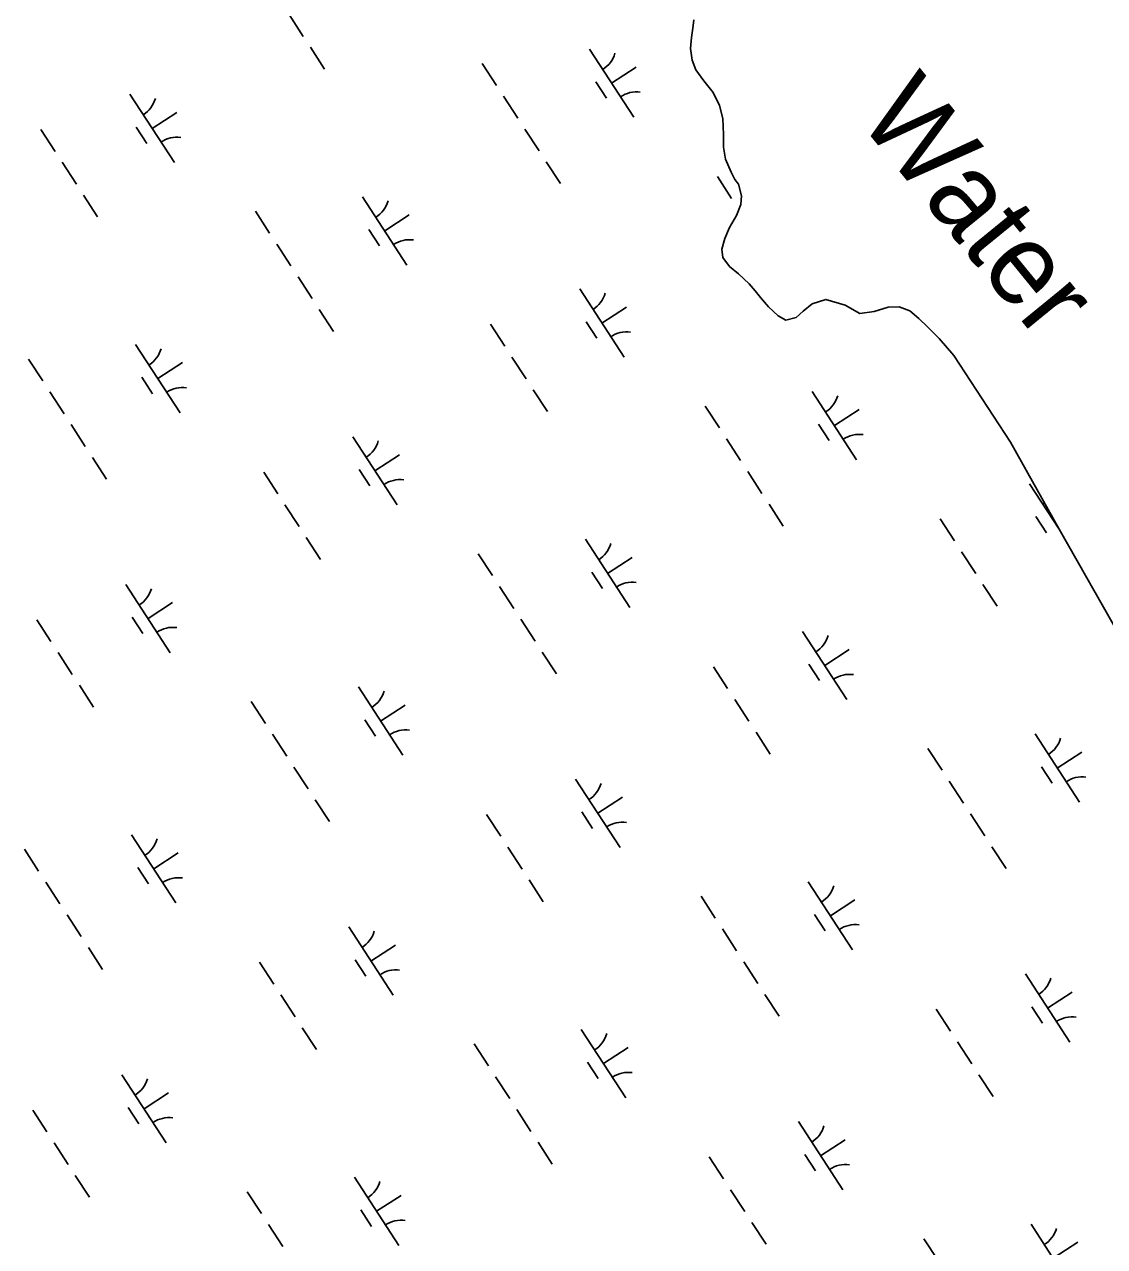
# Model space of a CAD drawing. Extents: x 3953924 to 3974542, y 193747 to 216192.
# Drawn here: x 3966671 to 3967335, y 205029 to 205780 of the extents above; entities that cross this region are included whole.
import ezdxf

# ---------------------------------------------------------------- set-up
doc = ezdxf.new("R2010")
doc.units = 0
for name, color, linetype in [('V-RIVR-IDEN', 7, 'Continuous'), ('V-TOPO-SHOR', 7, 'Continuous'), ('V-WETL-SWMP', 7, 'Continuous')]:
    doc.layers.add(name, color=color, linetype=linetype)

msp = doc.modelspace()

# ---------------------------------------------------------------- linework, layer by layer
at = {"layer": 'V-TOPO-SHOR'}
msp.add_lwpolyline([(3967082.61, 205782.77), (3967081.95, 205777.58), (3967081.04, 205771.89), (3967080.62, 205765.17), (3967081.47, 205757.95), (3967083.85, 205751.99), (3967088.63, 205745.25), (3967094.42, 205738), (3967098.43, 205730.12), (3967100.42, 205722.14), (3967100.87, 205712.25), (3967100.71, 205704.4), (3967102.06, 205697.05), (3967105.57, 205689.18), (3967107.83, 205684.61), (3967109.96, 205681.68), (3967111.83, 205674.58), (3967111.55, 205669.26), (3967108.73, 205662.44), (3967104.51, 205655.24), (3967101.56, 205648.41), (3967099.76, 205641.83), (3967100.49, 205636.76), (3967104.52, 205631.17), (3967109.94, 205626.71), (3967116.62, 205620.6), (3967120.27, 205616.27), (3967123.55, 205612.08), (3967128.46, 205606.35), (3967134.38, 205600.88), (3967139.06, 205598.19), (3967145.52, 205599.93), (3967149.72, 205603.84), (3967155.19, 205608.37), (3967163.69, 205610.99), (3967175.58, 205607.38), (3967184.55, 205602.27), (3967193.42, 205603.49), (3967201.92, 205606.24), (3967208.63, 205606.45), (3967215.21, 205604.01), (3967220.88, 205599.17), (3967226.18, 205594.21), (3967233.23, 205587.08), (3967242.3, 205576.64), (3967277.12, 205523.27), (3967306.99, 205469.8), (3967345.41, 205402.6)], dxfattribs=at)
at = {"layer": 'V-WETL-SWMP'}
for p, q in [((3966833.87, 205785.93), (3966842.6, 205772.52)), ((3967081.95, 205777.58), (3967082.61, 205782.77)), ((3967081.04, 205771.89), (3967081.95, 205777.58)), ((3966846.96, 205765.82), (3966855.69, 205752.41)), ((3967018.42, 205764.77), (3967045.7, 205722.86)), ((3967080.62, 205765.17), (3967081.04, 205771.89)), ((3967081.47, 205757.95), (3967080.62, 205765.17)), ((3967083.85, 205751.99), (3967081.47, 205757.95)), ((3966952.6, 205755.83), (3966961.33, 205742.43)), ((3967032.06, 205743.81), (3967047.14, 205753.63)), ((3967088.63, 205745.25), (3967083.85, 205751.99)), ((3967022.32, 205744.63), (3967028.87, 205734.58)), ((3967094.42, 205738), (3967088.63, 205745.25)), ((3966736.13, 205736.98), (3966763.4, 205695.08)), ((3966965.69, 205735.72), (3966974.42, 205722.31)), ((3967098.43, 205730.12), (3967094.42, 205738)), ((3967100.42, 205722.14), (3967098.43, 205730.12)), ((3966749.76, 205716.03), (3966764.85, 205725.85)), ((3967100.87, 205712.25), (3967100.42, 205722.14)), ((3966681.37, 205715.3), (3966690.1, 205701.89)), ((3966740.02, 205716.85), (3966746.57, 205706.79)), ((3966978.79, 205715.61), (3966987.52, 205702.2)), ((3967100.71, 205704.4), (3967100.87, 205712.25)), ((3967102.06, 205697.05), (3967100.71, 205704.4)), ((3967105.57, 205689.18), (3967102.06, 205697.05)), ((3966694.46, 205695.19), (3966703.19, 205681.78)), ((3966991.88, 205695.49), (3967000.61, 205682.08)), ((3967097.09, 205686.47), (3967105.81, 205673.06)), ((3967107.83, 205684.61), (3967105.57, 205689.18)), ((3967109.96, 205681.68), (3967107.83, 205684.61)), ((3966707.56, 205675.08), (3966716.28, 205661.67)), ((3967111.83, 205674.58), (3967109.96, 205681.68)), ((3967111.55, 205669.26), (3967111.83, 205674.58)), ((3966879.02, 205674.02), (3966906.29, 205632.12)), ((3967108.73, 205662.44), (3967111.55, 205669.26)), ((3966813.2, 205665.09), (3966821.92, 205651.68)), ((3966892.65, 205653.07), (3966907.74, 205662.89)), ((3967104.51, 205655.24), (3967108.73, 205662.44)), ((3967110.18, 205666.36), (3967110.28, 205666.2)), ((3966882.92, 205653.89), (3966889.46, 205643.83)), ((3967101.56, 205648.41), (3967104.51, 205655.24)), ((3966826.29, 205644.98), (3966835.02, 205631.57)), ((3967099.76, 205641.84), (3967101.56, 205648.41)), ((3967100.49, 205636.77), (3967099.76, 205641.84)), ((3967104.52, 205631.17), (3967100.49, 205636.77)), ((3967109.94, 205626.71), (3967104.52, 205631.17)), ((3966839.38, 205624.86), (3966848.11, 205611.45)), ((3967116.62, 205620.6), (3967109.94, 205626.71)), ((3967012.44, 205617.41), (3967039.71, 205575.5)), ((3967120.27, 205616.27), (3967116.62, 205620.6)), ((3967123.55, 205612.08), (3967120.27, 205616.27)), ((3967128.46, 205606.35), (3967123.55, 205612.08)), ((3967155.19, 205608.37), (3967149.72, 205603.84)), ((3967163.69, 205610.99), (3967155.19, 205608.37)), ((3967175.58, 205607.38), (3967163.69, 205610.99)), ((3967184.55, 205602.27), (3967175.58, 205607.38)), ((3966852.48, 205604.75), (3966861.2, 205591.34)), ((3967026.08, 205596.45), (3967041.16, 205606.27)), ((3967134.38, 205600.88), (3967128.46, 205606.35)), ((3967139.06, 205598.19), (3967134.38, 205600.88)), ((3967145.52, 205599.93), (3967139.06, 205598.19)), ((3967149.72, 205603.84), (3967145.52, 205599.93)), ((3967193.42, 205603.49), (3967184.55, 205602.27)), ((3967201.92, 205606.23), (3967193.42, 205603.49)), ((3967208.63, 205606.45), (3967201.92, 205606.23)), ((3967215.21, 205604.01), (3967208.63, 205606.45)), ((3967220.88, 205599.17), (3967215.21, 205604.01)), ((3966957.68, 205595.73), (3966966.41, 205582.32)), ((3967016.34, 205597.27), (3967022.88, 205587.22)), ((3967226.18, 205594.21), (3967220.88, 205599.17)), ((3967233.23, 205587.08), (3967226.18, 205594.21)), ((3967242.3, 205576.64), (3967233.23, 205587.08)), ((3966739.61, 205583.28), (3966766.89, 205541.37)), ((3966673.79, 205574.35), (3966682.52, 205560.94)), ((3966753.25, 205562.33), (3966768.34, 205572.15)), ((3966970.77, 205575.61), (3966979.5, 205562.2)), ((3967277.12, 205523.27), (3967242.3, 205576.64)), ((3966743.51, 205563.14), (3966750.06, 205553.09)), ((3966983.87, 205555.5), (3966992.6, 205542.09)), ((3967155.33, 205554.45), (3967182.6, 205512.54)), ((3966686.88, 205554.23), (3966695.61, 205540.82)), ((3967089.51, 205545.51), (3967098.24, 205532.11)), ((3967168.97, 205533.49), (3967184.05, 205543.31)), ((3966699.98, 205534.12), (3966708.71, 205520.71)), ((3967159.23, 205534.31), (3967165.77, 205524.26)), ((3966873.03, 205526.66), (3966900.31, 205484.76)), ((3967102.6, 205525.4), (3967111.33, 205511.99)), ((3967306.99, 205469.79), (3967277.12, 205523.27)), ((3966713.07, 205514), (3966721.8, 205500.59)), ((3966886.67, 205505.71), (3966901.76, 205515.53)), ((3966818.28, 205504.98), (3966827.01, 205491.57)), ((3966876.93, 205506.53), (3966883.48, 205496.47)), ((3967115.69, 205505.29), (3967124.42, 205491.88)), ((3967288.75, 205497.83), (3967306.95, 205469.87)), ((3966831.37, 205484.87), (3966840.1, 205471.46)), ((3967128.79, 205485.17), (3967137.51, 205471.76)), ((3967233.99, 205476.15), (3967242.72, 205462.74)), ((3967292.65, 205477.7), (3967299.19, 205467.64)), ((3967302.39, 205476.88), (3967302.86, 205477.19)), ((3966844.46, 205464.76), (3966853.19, 205451.35)), ((3967345.41, 205402.6), (3967306.99, 205469.79)), ((3967015.92, 205463.7), (3967043.2, 205421.8)), ((3966950.1, 205454.77), (3966958.83, 205441.36)), ((3967029.56, 205442.75), (3967044.65, 205452.57)), ((3967247.09, 205456.04), (3967255.81, 205442.63)), ((3967019.82, 205443.57), (3967026.37, 205433.51)), ((3966733.63, 205435.92), (3966760.91, 205394.01)), ((3966963.2, 205434.66), (3966971.92, 205421.25)), ((3967260.18, 205435.93), (3967268.91, 205422.52)), ((3966747.27, 205414.96), (3966762.35, 205424.78)), ((3966678.87, 205414.24), (3966687.6, 205400.83)), ((3966737.53, 205415.78), (3966744.07, 205405.73)), ((3966976.29, 205414.54), (3966985.02, 205401.13)), ((3967149.34, 205407.09), (3967176.62, 205365.18)), ((3966691.97, 205394.13), (3966700.69, 205380.72)), ((3966989.38, 205394.43), (3966998.11, 205381.02)), ((3967162.98, 205386.13), (3967178.07, 205395.95)), ((3967094.59, 205385.41), (3967103.32, 205372)), ((3967153.24, 205386.95), (3967159.79, 205376.9)), ((3966705.06, 205374.01), (3966713.79, 205360.6)), ((3966876.52, 205372.96), (3966903.8, 205331.05)), ((3966810.7, 205364.03), (3966819.43, 205350.62)), ((3966890.16, 205352.01), (3966905.24, 205361.83)), ((3967107.68, 205365.29), (3967116.41, 205351.89)), ((3966880.42, 205352.82), (3966886.96, 205342.77)), ((3967120.77, 205345.18), (3967129.5, 205331.77)), ((3966823.79, 205343.91), (3966832.52, 205330.5)), ((3967292.23, 205344.13), (3967319.51, 205302.22)), ((3967226.41, 205335.19), (3967235.14, 205321.79)), ((3967305.87, 205323.17), (3967320.96, 205332.99)), ((3966836.88, 205323.8), (3966845.61, 205310.39)), ((3967296.13, 205323.99), (3967302.68, 205313.94)), ((3967009.94, 205316.34), (3967037.22, 205274.44)), ((3967239.51, 205315.08), (3967248.24, 205301.67)), ((3966849.98, 205303.68), (3966858.71, 205290.27)), ((3967023.58, 205295.39), (3967038.66, 205305.21)), ((3966955.18, 205294.66), (3966963.91, 205281.25)), ((3967013.84, 205296.21), (3967020.38, 205286.15)), ((3967252.6, 205294.97), (3967261.33, 205281.56)), ((3966737.11, 205282.21), (3966764.39, 205240.31)), ((3966671.29, 205273.28), (3966680.02, 205259.87)), ((3966750.75, 205261.26), (3966765.84, 205271.08)), ((3966968.28, 205274.55), (3966977.01, 205261.14)), ((3967265.69, 205274.85), (3967274.42, 205261.44)), ((3966741.01, 205262.08), (3966747.56, 205252.02)), ((3966981.37, 205254.44), (3966990.1, 205241.03)), ((3966684.39, 205253.17), (3966693.12, 205239.76)), ((3967152.83, 205253.38), (3967180.11, 205211.48)), ((3967087.01, 205244.45), (3967095.74, 205231.04)), ((3967166.47, 205232.43), (3967181.55, 205242.25)), ((3966697.48, 205233.05), (3966706.21, 205219.64)), ((3967156.73, 205233.25), (3967163.28, 205223.19)), ((3966870.53, 205225.6), (3966897.81, 205183.69)), ((3967100.1, 205224.34), (3967108.83, 205210.93)), ((3966710.57, 205212.94), (3966719.3, 205199.53)), ((3966884.17, 205204.64), (3966899.26, 205214.46)), ((3966815.78, 205203.92), (3966824.51, 205190.51)), ((3966874.43, 205205.46), (3966880.98, 205195.41)), ((3967113.2, 205204.22), (3967121.92, 205190.81)), ((3967286.25, 205196.77), (3967313.53, 205154.86)), ((3966828.87, 205183.81), (3966837.6, 205170.4)), ((3967126.29, 205184.11), (3967135.02, 205170.7)), ((3967299.89, 205175.81), (3967314.97, 205185.63)), ((3967231.49, 205175.09), (3967240.22, 205161.68)), ((3967290.15, 205176.63), (3967296.7, 205166.58)), ((3966841.97, 205163.69), (3966850.69, 205150.28)), ((3967013.42, 205162.64), (3967040.7, 205120.73)), ((3966947.6, 205153.71), (3966956.33, 205140.3)), ((3967027.06, 205141.69), (3967042.15, 205151.51)), ((3967244.59, 205154.97), (3967253.32, 205141.57)), ((3967017.32, 205142.5), (3967023.87, 205132.45)), ((3966731.13, 205134.85), (3966758.41, 205092.95)), ((3967257.68, 205134.86), (3967266.41, 205121.45)), ((3966960.7, 205133.59), (3966969.43, 205120.18)), ((3966744.77, 205113.9), (3966759.85, 205123.72)), ((3966676.37, 205113.17), (3966685.1, 205099.77)), ((3966735.03, 205114.72), (3966741.58, 205104.66)), ((3966973.79, 205113.48), (3966982.52, 205100.07)), ((3967146.85, 205106.02), (3967174.12, 205064.12)), ((3966689.47, 205093.06), (3966698.2, 205079.65)), ((3966986.88, 205093.36), (3966995.61, 205079.95)), ((3967160.48, 205085.07), (3967175.57, 205094.89)), ((3967092.09, 205084.34), (3967100.82, 205070.93)), ((3967150.75, 205085.89), (3967157.29, 205075.83)), ((3966702.56, 205072.95), (3966711.29, 205059.54)), ((3966874.02, 205071.89), (3966901.3, 205029.99)), ((3966808.2, 205062.96), (3966816.93, 205049.55)), ((3966887.66, 205050.94), (3966902.74, 205060.76)), ((3967105.18, 205064.23), (3967113.91, 205050.82)), ((3966877.92, 205051.76), (3966884.47, 205041.7)), ((3967118.28, 205044.12), (3967127, 205030.71)), ((3966821.29, 205042.85), (3966830.02, 205029.44)), ((3967289.74, 205043.06), (3967317.01, 205001.16)), ((3967223.92, 205034.13), (3967232.64, 205020.72)), ((3967303.37, 205022.11), (3967318.46, 205031.93))]:
    msp.add_line(p, q, dxfattribs=at)
for centre, start, end in [((3967017.19, 205767.09), 302.29009, 343.83375), ((3967047.33, 205720.8), 82.29009, 123.83375), ((3966734.89, 205739.31), 302.29009, 343.83375), ((3966765.03, 205693.01), 82.29009, 123.83375), ((3966877.78, 205676.35), 302.29009, 343.83375), ((3966907.92, 205630.05), 82.29009, 123.83375), ((3967011.21, 205619.73), 302.29009, 343.83375), ((3967041.34, 205573.43), 82.29009, 123.83375), ((3966738.38, 205585.6), 302.29009, 343.83375), ((3966768.52, 205539.31), 82.29009, 123.83375), ((3967154.1, 205556.77), 302.29009, 343.83375), ((3967184.23, 205510.48), 82.29009, 123.83375), ((3966871.8, 205528.99), 302.29009, 343.83375), ((3966901.94, 205482.69), 82.29009, 123.83375), ((3967287.52, 205500.16), 302.29009, 306.33799), ((3967014.69, 205466.03), 302.29009, 343.83375), ((3967044.83, 205419.73), 82.29009, 123.83375), ((3966732.4, 205438.24), 302.29009, 343.83375), ((3966762.53, 205391.95), 82.29009, 123.83375), ((3967148.11, 205409.41), 302.29009, 343.83375), ((3967178.25, 205363.11), 82.29009, 123.83375), ((3966875.29, 205375.28), 302.29009, 343.83375), ((3966905.42, 205328.99), 82.29009, 123.83375), ((3967291, 205346.45), 302.29009, 343.83375), ((3967321.14, 205300.16), 82.29009, 123.83375), ((3967008.71, 205318.67), 302.29009, 343.83375), ((3967038.85, 205272.37), 82.29009, 123.83375), ((3966735.88, 205284.54), 302.29009, 343.83375), ((3966766.02, 205238.24), 82.29009, 123.83375), ((3967151.6, 205255.71), 302.29009, 343.83375), ((3967181.74, 205209.41), 82.29009, 123.83375), ((3966869.3, 205227.92), 302.29009, 343.83375), ((3966899.44, 205181.63), 82.29009, 123.83375), ((3967285.02, 205199.09), 302.29009, 343.83375), ((3967315.16, 205152.79), 82.29009, 123.83375), ((3967012.19, 205164.96), 302.29009, 343.83375), ((3967042.33, 205118.67), 82.29009, 123.83375), ((3966729.9, 205137.18), 302.29009, 343.83375), ((3966760.04, 205090.88), 82.29009, 123.83375), ((3967145.61, 205108.35), 302.29009, 343.83375), ((3967175.75, 205062.05), 82.29009, 123.83375), ((3966872.79, 205074.22), 302.29009, 343.83375), ((3966902.93, 205027.92), 82.29009, 123.83375), ((3967288.5, 205045.39), 302.29009, 343.83375)]:
    msp.add_arc(centre, 17.62, start, end, dxfattribs=at)

# ---------------------------------------------------------------- texts
at = {"layer": 'V-RIVR-IDEN'}
msp.add_text('Water', height=50, rotation=309.21796, dxfattribs=at).set_placement((3967182.38, 205722.03))

doc.saveas('drawing.dxf')
